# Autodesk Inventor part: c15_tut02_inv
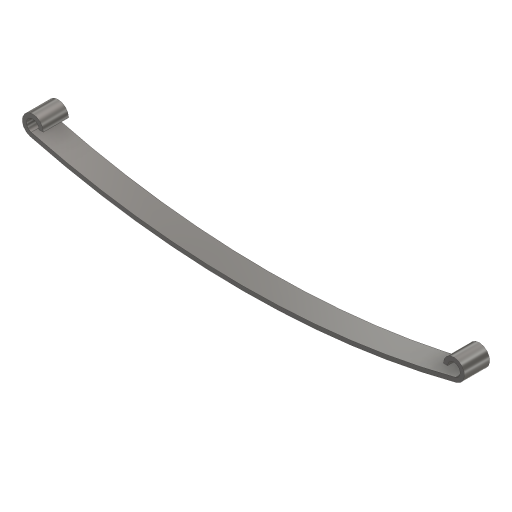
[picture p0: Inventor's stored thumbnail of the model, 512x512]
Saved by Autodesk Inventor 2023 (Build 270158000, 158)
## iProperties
Created: 2017-05
Part Number: c15_tut02_inv
Material: Steel, Mild
Document SubType Name: Modeling
Designer: CADCIM 00
Mass: 5.6491 g
Surface Area: 16.9114 cm^2
Volume: 0.71963 cm^3
Density: 7.85 g/cm^3
Appearance: Semi-Polished
Author: CADCIM 00
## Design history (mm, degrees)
sketch "Sketch1"
  geometry: L1 (0, 0)-(0, 18.068); L2 (48.5, 8.9)-(47.5, 8.9); L3 (-48.5, 8.9)-(-47.5, 8.9); A1 r 200 centre (0, 201) between (-50.378, 7.449) and (50.378, 7.449); A2 r 201 centre (0, 201) between (-50.63, 6.481) and (50.63, 6.481); A3 r 1.5 centre (50, 8.9) between (50.378, 7.449) and (48.5, 8.9); A4 r 2.5 centre (50, 8.9) between (50.63, 6.481) and (47.5, 8.9); A5 r 1.5 centre (-50, 8.9) between (-48.5, 8.9) and (-50.378, 7.449); A6 r 2.5 centre (-50, 8.9) between (-47.5, 8.9) and (-50.63, 6.481); 5 further points
  constraints: 13 point on circle, 6 centre point, 6 end point, 6 symmetric about line, 5 horizontal alignment, 3 coincident, 2 tangent, 1 horizontal, 1 midpoint, 1 vertical, 2 other
  dimensions: "d0" = 200 radius of A1; "d1" = 1 radial gap between concentric circles of A2 A1; "d2" = 2.5 radius of A4; "d3" = 50 distance from line of L1 A3.centre
extrude "Extrusion1" new body sketch "Sketch1" distance "d4" = 6; taper "d5" = 0 deg
body "Solid1"
